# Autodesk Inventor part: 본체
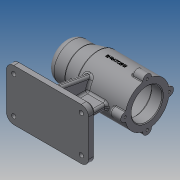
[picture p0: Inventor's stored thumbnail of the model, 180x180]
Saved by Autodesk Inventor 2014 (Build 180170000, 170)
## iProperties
Created: 2019-07
Part Number: 본체
Material: Generic
Document SubType Name: Modeling
Designer: kb542-7
Density: 1 g/cm^3
Appearance: Default
Author: kb542-7
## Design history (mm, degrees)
sketch "스케치1"
  geometry: L1 (-56, 0)-(-56, 25); L2 (-56, 25)-(-31, 25); L3 (-31, 25)-(-11, 30); L4 (-11, 30)-(56, 30); L5 (56, 30)-(56, 21); L6 (56, 0)-(-56, 0); L7 (-50, 0)-(-50, 10.5); L8 (-50, 10.5)-(-47, 10.5); L9 (-47, 10.5)-(-47, 16); L10 (-47, 16)-(-43, 16); L11 (-43, 16)-(-43, 17.5); L12 (-43, 17.5)-(-25, 17.5); L13 (-25, 17.5)-(-25, 21); L14 (-25, 21)-(-13, 21); L15 (-13, 21)-(-13, 24); L16 (-13, 24)-(41, 24); L17 (41, 24)-(41, 21); L18 (41, 21)-(56, 21); 2 further points
  constraints: 36 end point, 10 parallel, 5 perpendicular, 1 coincident, 1 horizontal, 1 midpoint, 1 point on line, 1 vertical, 1 vertical alignment
  dimensions: "d0" = 25 distance from line of L2.end L1; "d1" = 45 distance from line of L1 L3.end; "d3" = 60 diameter of L4 L6; "d4" = 50 diameter of L2 L6; "d12" = 42 diameter of L18 L6; "d13" = 112 distance between parallel lines of L1 L5; "d14" = 48 diameter of L16 L6; "d15" = 54 distance of L15.end L16.end; "d16" = 15 distance of L17.end L5.end; "d17" = 42 diameter of L14 L6; "d18" = 35 diameter of L12 L6; "d19" = 32 diameter of L10 L6; "d20" = 21 diameter of L8 L6; "d21" = 3 distance of L7.end L8.end; "d22" = 4 distance of L9.end L10.end; "d23" = 18 distance of L11.end L12.end; "d24" = 12 distance of L13.end L14.end
revolve "회전1" sketch "스케치1" stored, may be unused: angle "d5" = 90 deg
sketch "스케치4"
  geometry: L1 (-56, -70)-(56, -70); L2 (56, -70)-(56, -80); L3 (56, -80)-(-56, -80); L4 (-56, -80)-(-56, -70); 2 further points
  constraints: 8 end point, 2 parallel, 1 horizontal, 1 midpoint, 1 perpendicular, 1 vertical alignment
  dimensions: "d25" = 112 distance of L2.end L3.end; "d26" = 10 distance of L1.end L2.end; "d27" = 80 distance from line of L3 point (0, 0)
extrude "돌출2" join sketch "스케치4" stored distance "d28" = 70; taper "d29" = 0 deg
sketch "스케치5"
  geometry: L1 (-70, -35)-(-70, 35) reference; L2 (-22.666, 19.654)-(-70, 28); L3 (-22.666, -19.654)-(-70, -28); L4 (-70, 35)-(-80, 35) reference; L5 (-80, -35)-(-70, -35) reference; A1 r 30 centre (0, 0) between (-22.666, 19.654) and (-22.666, -19.654) reference; 1 further point
  constraints: 4 end point, 2 point on circle, 2 point on line
  dimensions: "d30" = 7 distance from line of L2.end L4; "d31" = 7 distance from line of L5 L3.end; "d33" = 100 deg angle of L1 L3; "d34" = 100 deg angle of L1 L2
extrude "돌출3" join sketch "스케치5" stored distance "d35" = 8; taper "d36" = 0 deg
sketch "스케치7"
  geometry: L1 (-31, -25)-(-11, -30) reference; L2 (-11, -30)-(56, -30) reference; L3 (-56, -25)-(-31, -25) reference; L4 (-56, -70)-(56, -70) reference; L5 (-20.57, -27.607)-(-36, -70); L6 (31, -70)-(31, -30); L7 (56, -70)-(56, -80) reference; L8 (-56, -80)-(-56, -70) reference; 1 further point
  constraints: 4 end point, 4 point on line, 1 perpendicular
  dimensions: "d37" = 25 distance between parallel lines of L7 L6; "d38" = 110 deg angle of L4 L5; "d39" = 20 distance from line of L5.end L8
feature "리브1" dims "d40" = 1, "d41" = 8, "d42" = 0, "d43" = 0, "d44" = 1, "d45" = 1
feature "리브2" dims "d46" = 1, "d47" = 8, "d48" = 0, "d49" = 0, "d50" = 1, "d51" = 1
sketch "스케치8"
  geometry: C1 r 21 at (0, 0) reference; A1 r 6 centre (0, 30) between (5.97, 29.4) and (-5.97, 29.4); A2 r 30 centre (0, 0) between (4, -29.732) and (-4, -29.732) reference; A3 r 30 centre (0, 0) between (4, -29.732) and (-4, -29.732) reference; 1 further point
  constraints: 6 point on circle, 1 centre point, 1 coincident, 1 vertical alignment
  dimensions: "d55" = 6 radius of A1
extrude "돌출4" join sketch "스케치8" distance "d56" = 16; taper "d57" = 0 deg
sketch "스케치9"
  geometry: A1 r 6 centre (0, 0) between (5.97, -0.6) and (-5.97, -0.6) reference; 1 further point
  constraints: 1 coincident
hole "구멍1" sketch "스케치9" at (0, 0) diameter "d58" = 3.242; stored, may be unused: countersink angle "d62" = 90 deg, drill point angle "d64" = 118 deg; dims "d59" = 8, "d60" = 4, "d61" = 2, "d63" = 11
fillet "모깎기2" dims "d66" = 3
fillet "모깎기3" dims "d67" = 1
fillet "모깎기4" dims "d71" = 10
sketch "스케치11"
  geometry: C1 r 3 at (0, -10); C2 r 3 at (92, -10); C3 r 3 at (92, -60); C4 r 3 at (0, -60); A1 r 10 centre (92, -60) between (92, -70) and (102, -60) reference; A2 r 10 centre (92, -10) between (102, -10) and (92, 0) reference; A3 r 10 centre (0, -10) between (0, 0) and (-10, -10) reference; A4 r 10 centre (0, -60) between (-10, -60) and (0, -70) reference; 1 further point
  constraints: 4 centre point, 4 coincident, 3 equal radius
  dimensions: "d73" = 6 diameter of C1
extrude "돌출5" cut sketch "스케치11" stored distance "d74" = 16; taper "d75" = 0 deg
chamfer "모따기1" distance "d76" = 3; stored, may be unused: second distance "d77" = 2, angle "d78" = 45 deg
fillet "모깎기5" dims "d79" = 3
fillet "모깎기6" dims "d80" = 3
chamfer "모따기2" distance "d81" = 1; stored, may be unused: second distance "d82" = 2, angle "d83" = 45 deg
fillet "모깎기7" dims "d84" = 10
fillet "모깎기8" dims "d85" = 3
fillet "모깎기9" dims "d86" = 3
fillet "모깎기10" dims "d87" = 3
node "작업 평면1"
sketch "스케치12"
  geometry: L1 (56, 6.771)-(56, 29.226) reference; 2 further points
  constraints: 1 horizontal alignment, 1 other
  dimensions: "d89" = 42 distance from line of L1 point (14, 0)
feature "엠보싱1" sketch "스케치12" dims "d21" = 3, "d90" = 0.5, "d91" = 0
fillet "모깎기11" dims "d92" = 0.3
fillet "모깎기12" dims "d93" = 3
node "솔리드1"
pattern_circular "원형 패턴1" dims "d69" = 360 deg
